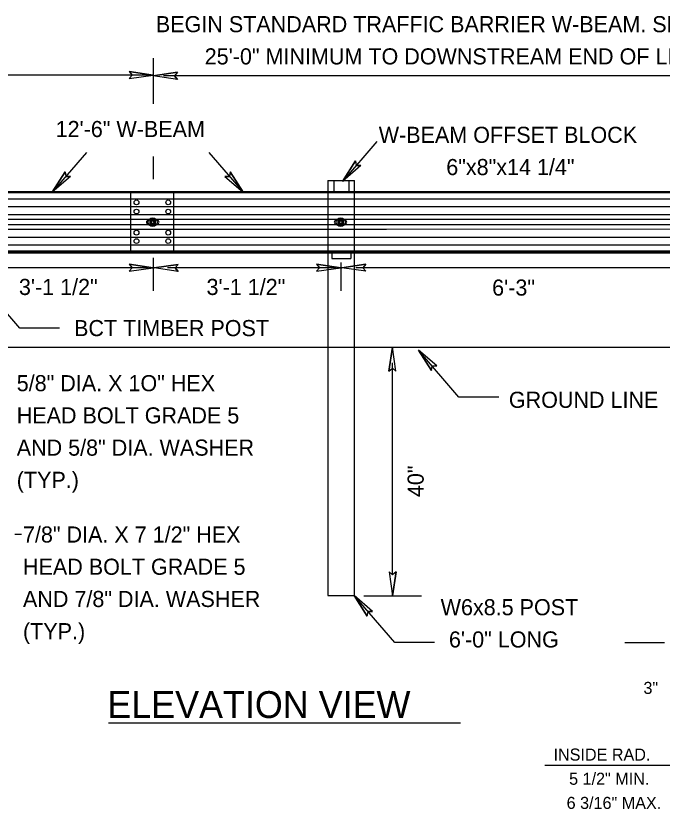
# Model space of a CAD drawing. Extents: x 12.2 to 54.5, y -7.8 to 16.1.
# Drawn here: x 15.289 to 17.698, y 12.917 to 15.871 of the extents above; entities that cross this region are included whole.
import ezdxf

# ---------------------------------------------------------------- set-up
doc = ezdxf.new("R2010")
doc.units = 0
for name, color, linetype in [('BORD-LINE', 7, 'Continuous'), ('DETL-DIMS', 7, 'Continuous'), ('DETL-LINE', 7, 'Continuous'), ('DETL-NOTE', 7, 'Continuous'), ('DETL-TITL', 7, 'Continuous')]:
    doc.layers.add(name, color=color, linetype=linetype)

msp = doc.modelspace()

# ---------------------------------------------------------------- linework, layer by layer
at = {"layer": 'BORD-LINE'}
for p, q in [((16.4521, 15.2577), (16.4521, 15.2153)), ((16.4521, 15.2577), (16.5509, 15.2577)), ((16.4743, 15.2577), (16.4743, 15.217)), ((16.5302, 15.2577), (16.5302, 15.2159)), ((16.5506, 15.2577), (16.5506, 15.217)), ((15.4389, 15.2124), (15.1499, 15.2124)), ((16.7003, 15.2118), (15.1503, 15.2114)), ((16.701, 15.216), (15.1504, 15.2157)), ((16.4521, 15.2244), (16.4521, 14.9898)), ((16.5504, 15.2244), (16.5504, 14.9898)), ((18.8504, 15.2118), (16.7003, 15.2118)), ((18.8462, 15.2162), (16.701, 15.216)), ((16.6947, 15.1888), (15.1499, 15.1888)), ((18.8663, 15.1891), (16.6947, 15.1888)), ((16.6898, 15.1599), (15.1504, 15.1599)), ((18.8758, 15.1602), (16.6898, 15.1599)), ((16.6823, 15.1297), (15.1502, 15.1297)), ((18.8788, 15.13), (16.6823, 15.1297)), ((16.6793, 15.1131), (15.1505, 15.1131)), ((15.8161, 15.1098), (15.7833, 15.1098)), ((15.7833, 15.0958), (15.8161, 15.0958)), ((15.7886, 15.1086), (15.7886, 15.0971)), ((15.8097, 15.0971), (15.8097, 15.1086)), ((16.5156, 15.1098), (16.4828, 15.1098)), ((16.4828, 15.0958), (16.5156, 15.0958)), ((16.4894, 15.1086), (16.4894, 15.0971)), ((16.5105, 15.0971), (16.5105, 15.1086)), ((18.8785, 15.1135), (16.6793, 15.1131)), ((16.6747, 15.0925), (15.1505, 15.0925)), ((16.6708, 15.076), (15.1505, 15.076)), ((18.8725, 15.0763), (16.6708, 15.076)), ((18.8752, 15.0928), (16.6747, 15.0925)), ((16.6643, 15.0457), (15.1504, 15.0457)), ((18.8704, 15.046), (16.6643, 15.0457)), ((16.6586, 15.0169), (15.1503, 15.0169)), ((18.8799, 15.0172), (16.6586, 15.0169)), ((16.6539, 14.9942), (15.1504, 14.9942)), ((16.6525, 14.99), (15.1506, 14.99)), ((16.6522, 14.9875), (15.1506, 14.9875)), ((16.4521, 14.9898), (16.4521, 14.6369)), ((16.4663, 14.9875), (16.4663, 14.9675)), ((16.5377, 14.9874), (16.5377, 14.9675)), ((16.5504, 14.9898), (16.5504, 14.6366)), ((18.906, 14.988), (16.6522, 14.9875)), ((18.9034, 14.9903), (16.6525, 14.99)), ((18.8992, 14.9945), (16.6539, 14.9942)), ((16.4663, 14.9675), (16.5377, 14.9675)), ((12.3965, 14.6369), (18.9405, 14.6369)), ((16.4521, 14.6356), (16.4521, 13.7127)), ((16.5504, 14.6366), (16.5504, 13.7127)), ((16.4521, 13.7127), (16.5504, 13.7127))]:
    msp.add_line(p, q, dxfattribs=at)
for points in [[(15.7991, 15.1087), (15.7975, 15.1086), (15.7959, 15.1083), (15.7944, 15.1079), (15.7931, 15.1073), (15.7919, 15.1066), (15.791, 15.1057), (15.7903, 15.1048), (15.7899, 15.1038), (15.7898, 15.1028), (15.7899, 15.1018), (15.7903, 15.1008), (15.791, 15.0999), (15.7919, 15.0991), (15.7931, 15.0983), (15.7944, 15.0978), (15.7959, 15.0973), (15.7975, 15.0971), (15.7991, 15.097)], [(15.7991, 15.097), (15.8007, 15.0971), (15.8023, 15.0973), (15.8038, 15.0978), (15.8051, 15.0983), (15.8063, 15.0991), (15.8072, 15.0999), (15.8079, 15.1008), (15.8083, 15.1018), (15.8085, 15.1028), (15.8083, 15.1038), (15.8079, 15.1048), (15.8072, 15.1057), (15.8063, 15.1066), (15.8051, 15.1073), (15.8038, 15.1079), (15.8023, 15.1083), (15.8007, 15.1086), (15.7991, 15.1087)], [(16.5, 15.1087), (16.4984, 15.1086), (16.4968, 15.1083), (16.4953, 15.1079), (16.494, 15.1073), (16.4928, 15.1066), (16.4919, 15.1057), (16.4912, 15.1048), (16.4908, 15.1038), (16.4906, 15.1028), (16.4908, 15.1018), (16.4912, 15.1008), (16.4919, 15.0999), (16.4928, 15.0991), (16.494, 15.0983), (16.4953, 15.0978), (16.4968, 15.0973), (16.4984, 15.0971), (16.5, 15.097)], [(16.5, 15.097), (16.5016, 15.0971), (16.5032, 15.0973), (16.5047, 15.0978), (16.506, 15.0983), (16.5072, 15.0991), (16.5081, 15.0999), (16.5088, 15.1008), (16.5092, 15.1018), (16.5093, 15.1028), (16.5092, 15.1038), (16.5088, 15.1048), (16.5081, 15.1057), (16.5072, 15.1066), (16.506, 15.1073), (16.5047, 15.1079), (16.5032, 15.1083), (16.5016, 15.1086), (16.5, 15.1087)]]:
    msp.add_lwpolyline(points, dxfattribs=at)
for centre, radius in [((15.7991, 15.1028), 0.0164), ((15.7991, 15.1028), 0.00702), ((15.7991, 15.1028), 0.00614), ((15.7991, 15.1028), 0.00585), ((15.7991, 15.1028), 0.00498), ((16.5, 15.1028), 0.0164), ((16.5, 15.1028), 0.00702), ((16.5, 15.1028), 0.00614), ((16.5, 15.1028), 0.00585), ((16.5, 15.1028), 0.00498)]:
    msp.add_circle(centre, radius, dxfattribs=at)
for centre, radius, start, end in [((15.7833, 15.1028), 0.00702, 90.0039, 269.9961), ((15.7991, 15.1028), 0.012, 28.6537, 151.3463), ((15.7991, 15.1028), 0.012, 208.653, 331.347), ((15.7991, 15.1028), 0.00879, 120.0035, 179.9936), ((15.7991, 15.1028), 0.00879, 180.0054, 239.9976), ((15.7991, 15.1028), 0.00878, 59.9996, 120.0004), ((15.7991, 15.1028), 0.00878, 239.9975, 300.0025), ((15.7991, 15.1028), 0.00643, 57.8729, 122.1271), ((15.7991, 15.1028), 0.00643, 237.8729, 302.1271), ((15.7991, 15.1028), 0.00879, 0.0064, 59.9965), ((15.7991, 15.1028), 0.00879, 300.0024, 359.9946), ((15.8161, 15.1028), 0.00702, 270.0039, 89.9961), ((16.4828, 15.1028), 0.00702, 90.0039, 269.9961), ((16.5, 15.1028), 0.012, 28.6537, 151.3463), ((16.5, 15.1028), 0.012, 208.653, 331.347), ((16.5, 15.1028), 0.00879, 120.0035, 179.9936), ((16.5, 15.1028), 0.00879, 180.0054, 239.9976), ((16.5, 15.1028), 0.00878, 59.9996, 120.0004), ((16.5, 15.1028), 0.00878, 239.9975, 300.0025), ((16.5, 15.1028), 0.00643, 57.8729, 122.1271), ((16.5, 15.1028), 0.00643, 237.8729, 302.1271), ((16.5, 15.1028), 0.00879, 0.0064, 59.9965), ((16.5, 15.1028), 0.00879, 300.0024, 359.9946), ((16.5156, 15.1028), 0.00702, 270.0039, 89.9961)]:
    msp.add_arc(centre, radius, start, end, dxfattribs=at)
for points in [[(15.7903, 15.1079), (15.791, 15.1083), (15.7925, 15.1091), (15.7939, 15.11), (15.7947, 15.1104), (15.7947, 15.1104)], [(15.7903, 15.1079), (15.7903, 15.1075), (15.7903, 15.1064), (15.7903, 15.1047), (15.7903, 15.1035), (15.7903, 15.1028)], [(15.7903, 15.1028), (15.7903, 15.1027), (15.7903, 15.1019), (15.7903, 15.1006), (15.7903, 15.099), (15.7903, 15.098), (15.7903, 15.0978)], [(15.7947, 15.0952), (15.7941, 15.0956), (15.7929, 15.0963), (15.7914, 15.0971), (15.7906, 15.0976), (15.7903, 15.0978)], [(15.7947, 15.1104), (15.7953, 15.1108), (15.7966, 15.1115), (15.798, 15.1123), (15.7989, 15.1128), (15.7991, 15.113)], [(15.7991, 15.0927), (15.7984, 15.0931), (15.797, 15.0939), (15.7955, 15.0948), (15.7947, 15.0952), (15.7947, 15.0952)], [(15.7991, 15.113), (15.7998, 15.1126), (15.8013, 15.1117), (15.8027, 15.1109), (15.8035, 15.1104), (15.8035, 15.1104)], [(15.8035, 15.0952), (15.8029, 15.0949), (15.8017, 15.0942), (15.8002, 15.0933), (15.7994, 15.0928), (15.7991, 15.0927)], [(15.8035, 15.1104), (15.8041, 15.1101), (15.8053, 15.1094), (15.8068, 15.1085), (15.8077, 15.108), (15.8079, 15.1079)], [(15.8079, 15.0978), (15.8072, 15.0974), (15.8058, 15.0965), (15.8043, 15.0957), (15.8035, 15.0952), (15.8035, 15.0952)], [(15.8079, 15.1079), (15.8079, 15.1075), (15.8079, 15.1064), (15.8079, 15.1047), (15.8079, 15.1035), (15.8079, 15.1028)], [(15.8079, 15.1028), (15.8079, 15.1027), (15.8079, 15.1019), (15.8079, 15.1006), (15.8079, 15.099), (15.8079, 15.098), (15.8079, 15.0978)], [(16.4912, 15.1079), (16.4919, 15.1083), (16.4933, 15.1091), (16.4948, 15.11), (16.4956, 15.1104), (16.4956, 15.1104)], [(16.4912, 15.1079), (16.4912, 15.1075), (16.4912, 15.1064), (16.4912, 15.1047), (16.4912, 15.1035), (16.4912, 15.1028)], [(16.4912, 15.1028), (16.4912, 15.1027), (16.4912, 15.1019), (16.4912, 15.1006), (16.4912, 15.099), (16.4912, 15.098), (16.4912, 15.0978)], [(16.4956, 15.0952), (16.495, 15.0956), (16.4938, 15.0963), (16.4923, 15.0971), (16.4914, 15.0976), (16.4912, 15.0978)], [(16.4956, 15.1104), (16.4962, 15.1108), (16.4974, 15.1115), (16.4989, 15.1123), (16.4997, 15.1128), (16.5, 15.113)], [(16.5, 15.0927), (16.4993, 15.0931), (16.4978, 15.0939), (16.4964, 15.0948), (16.4956, 15.0952), (16.4956, 15.0952)], [(16.5, 15.113), (16.5007, 15.1126), (16.5021, 15.1117), (16.5036, 15.1109), (16.5044, 15.1104), (16.5044, 15.1104)], [(16.5044, 15.0952), (16.5038, 15.0949), (16.5025, 15.0942), (16.5011, 15.0933), (16.5002, 15.0928), (16.5, 15.0927)], [(16.5044, 15.1104), (16.505, 15.1101), (16.5062, 15.1094), (16.5077, 15.1085), (16.5085, 15.108), (16.5088, 15.1079)], [(16.5088, 15.0978), (16.5081, 15.0974), (16.5066, 15.0965), (16.5052, 15.0957), (16.5044, 15.0952), (16.5044, 15.0952)], [(16.5088, 15.1079), (16.5088, 15.1075), (16.5088, 15.1064), (16.5088, 15.1047), (16.5088, 15.1035), (16.5088, 15.1028)], [(16.5088, 15.1028), (16.5088, 15.1027), (16.5088, 15.1019), (16.5088, 15.1006), (16.5088, 15.099), (16.5088, 15.098), (16.5088, 15.0978)]]:
    msp.add_open_spline(points, degree=3, dxfattribs=at)
at = {"layer": 'DETL-DIMS'}
for p, q in [((15.8022, 15.5437), (15.8022, 15.7135)), ((15.7117, 15.6633), (15.8013, 15.6501)), ((15.7117, 15.6633), (15.7228, 15.6501)), ((15.8912, 15.6607), (15.8016, 15.6475)), ((15.8912, 15.6607), (15.8801, 15.6475)), ((15.8032, 15.6501), (12.6898, 15.6501)), ((15.7117, 15.6372), (15.8013, 15.6501)), ((15.7117, 15.6372), (15.7228, 15.6501)), ((15.8912, 15.6346), (15.8016, 15.6475)), ((19.0481, 15.6475), (15.8393, 15.6475)), ((15.8912, 15.6346), (15.8801, 15.6475)), ((16.6351, 15.4031), (16.5069, 15.2545)), ((15.5527, 15.3626), (15.4245, 15.2139)), ((16.0085, 15.3626), (16.1367, 15.2139)), ((15.8022, 15.263), (15.8022, 15.3479)), ((16.5554, 15.3309), (16.5069, 15.2545)), ((16.5554, 15.3309), (16.5582, 15.3139)), ((16.5752, 15.3139), (16.5069, 15.2545)), ((16.5752, 15.3139), (16.5582, 15.3139)), ((15.473, 15.2904), (15.4245, 15.2139)), ((15.4928, 15.2734), (15.4245, 15.2139)), ((15.473, 15.2904), (15.4758, 15.2734)), ((15.4928, 15.2734), (15.4758, 15.2734)), ((16.0685, 15.2734), (16.1367, 15.2139)), ((16.0685, 15.2734), (16.0855, 15.2734)), ((16.0882, 15.2904), (16.0855, 15.2734)), ((16.0882, 15.2904), (16.1367, 15.2139)), ((15.7182, 14.989), (15.7182, 15.2162)), ((15.878, 14.988), (15.878, 15.2152)), ((15.7111, 14.946), (15.8007, 14.9328)), ((15.7111, 14.946), (15.7222, 14.9328)), ((15.8026, 14.8471), (15.8026, 14.9706)), ((16.4103, 14.946), (16.4999, 14.9328)), ((16.4103, 14.946), (16.4214, 14.9328)), ((16.5018, 14.8471), (16.5018, 14.9532)), ((16.5937, 14.946), (16.5041, 14.9328)), ((16.5937, 14.946), (16.5826, 14.9328)), ((15.7829, 14.9328), (15.1551, 14.9328)), ((15.7111, 14.9199), (15.8007, 14.9328)), ((15.7111, 14.9199), (15.7222, 14.9328)), ((15.894, 14.9456), (15.8044, 14.9324)), ((15.894, 14.9195), (15.8044, 14.9324)), ((16.4821, 14.9328), (15.8543, 14.9328)), ((15.894, 14.9456), (15.8829, 14.9324)), ((15.894, 14.9195), (15.8829, 14.9324)), ((16.4103, 14.9199), (16.4999, 14.9328)), ((16.4103, 14.9199), (16.4214, 14.9328)), ((16.5937, 14.9199), (16.5041, 14.9328)), ((17.9011, 14.9328), (16.5563, 14.9328)), ((16.5937, 14.9199), (16.5826, 14.9328)), ((15.3039, 14.7084), (15.1528, 14.8836)), ((15.4524, 14.7084), (15.3039, 14.7084)), ((16.6798, 14.5477), (16.693, 14.6373)), ((16.7059, 14.5477), (16.693, 14.6373)), ((16.9405, 14.4515), (16.7895, 14.6267)), ((16.838, 14.5502), (16.7895, 14.6267)), ((16.8577, 14.5673), (16.7895, 14.6267)), ((16.6933, 13.7901), (16.6933, 14.5789)), ((16.838, 14.5502), (16.8407, 14.5672)), ((16.8577, 14.5673), (16.8407, 14.5672)), ((16.6798, 14.5477), (16.693, 14.5588)), ((16.7059, 14.5477), (16.693, 14.5588)), ((17.089, 14.4515), (16.9405, 14.4515)), ((15.3109, 13.9398), (15.2859, 13.9398)), ((16.6804, 13.8012), (16.6933, 13.7116)), ((16.6804, 13.8012), (16.6933, 13.7901)), ((16.7065, 13.8012), (16.6933, 13.7116)), ((16.7065, 13.8012), (16.6933, 13.7901)), ((16.7015, 13.5375), (16.5504, 13.7127)), ((16.5989, 13.6362), (16.5504, 13.7127)), ((16.6187, 13.6532), (16.5504, 13.7127)), ((16.5859, 13.7116), (16.8006, 13.7116)), ((16.5989, 13.6362), (16.6017, 13.6532)), ((16.6187, 13.6532), (16.6017, 13.6532)), ((16.8499, 13.5375), (16.7015, 13.5375)), ((17.5585, 13.5375), (17.707, 13.5375)), ((17.8835, 13.0791), (17.2601, 13.0791))]:
    msp.add_line(p, q, dxfattribs=at)
for points in [[(15.7117, 15.6372), (15.8013, 15.6501), (15.7117, 15.6633), (15.7228, 15.6501)], [(15.8912, 15.6346), (15.8016, 15.6475), (15.8912, 15.6607), (15.8801, 15.6475)], [(16.5752, 15.3139), (16.5069, 15.2545), (16.5554, 15.3309), (16.5582, 15.3139)], [(15.4928, 15.2734), (15.4245, 15.2139), (15.473, 15.2904), (15.4758, 15.2734)], [(16.0685, 15.2734), (16.1367, 15.2139), (16.0882, 15.2904), (16.0855, 15.2734)], [(15.7111, 14.9199), (15.8007, 14.9328), (15.7111, 14.946), (15.7222, 14.9328)], [(16.4103, 14.9199), (16.4999, 14.9328), (16.4103, 14.946), (16.4214, 14.9328)], [(16.5937, 14.9199), (16.5041, 14.9328), (16.5937, 14.946), (16.5826, 14.9328)], [(15.894, 14.9195), (15.8044, 14.9324), (15.894, 14.9456), (15.8829, 14.9324)], [(16.7059, 14.5477), (16.693, 14.6373), (16.6798, 14.5477), (16.693, 14.5588)], [(16.8577, 14.5673), (16.7895, 14.6267), (16.838, 14.5502), (16.8407, 14.5672)], [(16.6804, 13.8012), (16.6933, 13.7116), (16.7065, 13.8012), (16.6933, 13.7901)], [(16.6187, 13.6532), (16.5504, 13.7127), (16.5989, 13.6362), (16.6017, 13.6532)]]:
    msp.add_lwpolyline(points, close=True, dxfattribs=at)
at = {"layer": 'DETL-LINE'}
for centre in [(15.7389, 15.1765), (15.8573, 15.1765), (15.7389, 15.1421), (15.8573, 15.1421), (15.7389, 15.0637), (15.8573, 15.0637), (15.7389, 15.0323), (15.8573, 15.0323)]:
    msp.add_circle(centre, 0.00883, dxfattribs=at)
at = {"layer": 'DETL-TITL'}
msp.add_line((15.6343, 13.238), (16.947, 13.238), dxfattribs=at)

# ---------------------------------------------------------------- texts
at = {"layer": 'DETL-NOTE'}
for s, height, p in [('BEGIN STANDARD TRAFFIC BARRIER W-BEAM. SEE STD. MD 605.23', 0.06, (15.8111, 15.8101)), ('25\'-0" MINIMUM TO DOWNSTREAM END OF LENGTH OF NEED. ', 0.06, (15.9932, 15.6901)), ('12\'-6" W-BEAM', 0.06, (15.4375, 15.4196)), ('W-BEAM OFFSET BLOCK', 0.06, (16.6417, 15.398)), ('6"x8"x14 1/4" ', 0.06, (16.8934, 15.278)), ('3\'-1 1/2"', 0.06, (15.3008, 14.8316)), ('3\'-1 1/2"', 0.06, (16, 14.8316)), ('6\'-3"', 0.06, (17.0643, 14.8293)), ('BCT TIMBER POST', 0.06, (15.5063, 14.6784)), ('5/8" DIA. X 1O" HEX', 0.06, (15.2926, 14.4733)), ('GROUND LINE', 0.06, (17.1267, 14.4114)), ('HEAD BOLT GRADE 5', 0.06, (15.2926, 14.3533)), ('AND 5/8" DIA. WASHER', 0.06, (15.2926, 14.2333)), ('(TYP.)', 0.06, (15.2926, 14.1133)), ('7/8" DIA. X 7 1/2" HEX', 0.06, (15.3159, 13.9098)), ('HEAD BOLT GRADE 5', 0.06, (15.3159, 13.7898)), ('AND 7/8" DIA. WASHER', 0.06, (15.3159, 13.6698)), ('W6x8.5 POST', 0.06, (16.8725, 13.6391)), ('(TYP.)', 0.06, (15.3159, 13.5498)), ('6\'-0" LONG', 0.06, (16.9033, 13.5191)), ('3"', 0.045, (17.6282, 13.3461)), ('INSIDE RAD.', 0.045, (17.2931, 13.0979)), ('5 1/2" MIN.', 0.045, (17.3512, 13.0079)), ('6 3/16" MAX.', 0.045, (17.3419, 12.9179))]:
    msp.add_text(s, height=height, dxfattribs=at).set_placement(p)
msp.add_text('40"', height=0.06, rotation=90, dxfattribs=at).set_placement((16.8092, 14.079))
at = {"layer": 'DETL-TITL'}
msp.add_text('ELEVATION VIEW', height=0.1, dxfattribs=at).set_placement((15.6302, 13.2565))

doc.saveas('drawing.dxf')
